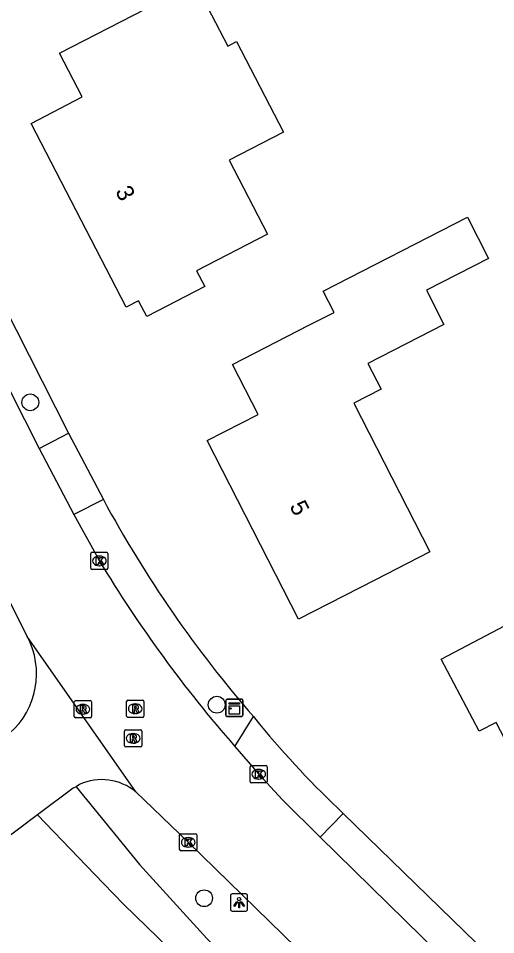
# Model space of a CAD drawing. Extents: x 162722 to 165099, y 384721 to 386283.
# Drawn here: x 163702.6 to 163730.3, y 384930.1 to 384983.4 of the extents above; entities that cross this region are included whole.
import ezdxf

# ---------------------------------------------------------------- set-up
doc = ezdxf.new("R2010")
doc.units = 0
for name, color, linetype in [('IMGEO_Boom', 7, 'Continuous'), ('IMGEO_Kast', 7, 'Continuous'), ('IMGEO_Kolk', 7, 'Continuous'), ('IMGEO_Lichtpunt', 7, 'Continuous'), ('IMGEO_Pand', 7, 'Continuous'), ('IMGEO_Pand_nummerreeks', 7, 'Continuous'), ('IMGEO_Parkeervlak_open', 7, 'Continuous'), ('IMGEO_Rijbaan_lokaal_open', 7, 'Continuous'), ('IMGEO_Rioolput', 7, 'Continuous'), ('IMGEO_Voetpad_open', 7, 'Continuous')]:
    doc.layers.add(name, color=color, linetype=linetype)

msp = doc.modelspace()

# ---------------------------------------------------------------- linework, layer by layer
at = {"layer": 'IMGEO_Boom'}
for centre in [(163703.26, 384961.042), (163714.111, 384943.457), (163713.375, 384932.201)]:
    msp.add_circle(centre, 0.489, dxfattribs=at)
at = {"layer": 'IMGEO_Kast'}
for p, q in [((163714.639, 384942.85), (163714.639, 384943.691)), ((163714.639, 384943.691), (163714.639, 384942.85)), ((163714.714, 384943.775), (163715.555, 384943.775)), ((163715.555, 384943.775), (163714.714, 384943.775)), ((163715.639, 384943.7), (163715.639, 384942.859)), ((163715.639, 384942.859), (163715.639, 384943.7)), ((163715.564, 384942.775), (163714.723, 384942.775)), ((163714.723, 384942.775), (163715.564, 384942.775))]:
    msp.add_line(p, q, dxfattribs=at)
for points in [[(163714.834, 384943.565), (163715.434, 384943.565), (163715.434, 384943.48), (163714.834, 384943.48), (163714.834, 384943.565)], [(163714.834, 384943.39), (163715.434, 384943.39), (163715.434, 384942.901), (163714.834, 384942.901), (163714.834, 384943.39)]]:
    msp.add_lwpolyline(points, dxfattribs=at)
msp.add_circle((163714.918, 384943.239), 0.0377, dxfattribs=at)
for centre, start, end in [((163714.717, 384943.697), 92.4484, 184.2845), ((163714.717, 384943.697), 92.4484, 184.2845), ((163715.561, 384943.697), 2.4484, 94.2845), ((163715.561, 384943.697), 2.4484, 94.2845), ((163714.717, 384942.853), 182.4484, 274.2845), ((163714.717, 384942.853), 182.4484, 274.2845), ((163715.561, 384942.853), 272.4484, 4.2845), ((163715.561, 384942.853), 272.4484, 4.2845)]:
    msp.add_arc(centre, 0.0779, start, end, dxfattribs=at)
at = {"layer": 'IMGEO_Kolk'}
for p, q in [((163706.78, 384951.395), (163706.78, 384952.247)), ((163706.855, 384952.321), (163707.707, 384952.321)), ((163707.268, 384952.101), (163707.293, 384952.101)), ((163707.781, 384952.247), (163707.781, 384951.395)), ((163707.291, 384951.541), (163707.266, 384951.541)), ((163707.707, 384951.321), (163706.855, 384951.321)), ((163716.051, 384938.988), (163716.051, 384939.84)), ((163716.126, 384939.914), (163716.978, 384939.914)), ((163716.539, 384939.694), (163716.564, 384939.694)), ((163717.052, 384939.84), (163717.052, 384938.988)), ((163716.562, 384939.134), (163716.537, 384939.134)), ((163716.978, 384938.914), (163716.126, 384938.914)), ((163712.026, 384935.954), (163712.878, 384935.954)), ((163711.951, 384935.028), (163711.951, 384935.88)), ((163712.439, 384935.734), (163712.464, 384935.734)), ((163712.952, 384935.88), (163712.952, 384935.028)), ((163712.878, 384934.954), (163712.026, 384934.954)), ((163712.462, 384935.174), (163712.437, 384935.174))]:
    msp.add_line(p, q, dxfattribs=at)
for points in [[(163706.78, 384951.395), (163706.78, 384952.247)], [(163706.855, 384952.321), (163707.707, 384952.321)], [(163707.101, 384952.021), (163707.224, 384952.021), (163707.224, 384951.87), (163707.354, 384952.021), (163707.518, 384952.021), (163707.372, 384951.87), (163707.525, 384951.621), (163707.373, 384951.621), (163707.288, 384951.785), (163707.224, 384951.718), (163707.224, 384951.621), (163707.101, 384951.621), (163707.101, 384952.021)], [(163707.781, 384952.247), (163707.781, 384951.395)], [(163707.707, 384951.321), (163706.855, 384951.321)], [(163716.051, 384938.988), (163716.051, 384939.84)], [(163716.126, 384939.914), (163716.978, 384939.914)], [(163717.052, 384939.84), (163717.052, 384938.988)], [(163716.372, 384939.614), (163716.495, 384939.614), (163716.495, 384939.463), (163716.625, 384939.614), (163716.789, 384939.614), (163716.643, 384939.463), (163716.796, 384939.214), (163716.644, 384939.214), (163716.559, 384939.378), (163716.495, 384939.311), (163716.495, 384939.214), (163716.372, 384939.214), (163716.372, 384939.614)], [(163716.978, 384938.914), (163716.126, 384938.914)], [(163712.026, 384935.954), (163712.878, 384935.954)], [(163711.951, 384935.028), (163711.951, 384935.88)], [(163712.272, 384935.654), (163712.395, 384935.654), (163712.395, 384935.503), (163712.525, 384935.654), (163712.689, 384935.654), (163712.543, 384935.503), (163712.696, 384935.254), (163712.544, 384935.254), (163712.459, 384935.418), (163712.395, 384935.351), (163712.395, 384935.254), (163712.272, 384935.254), (163712.272, 384935.654)], [(163712.952, 384935.88), (163712.952, 384935.028)], [(163712.878, 384934.954), (163712.026, 384934.954)]]:
    msp.add_lwpolyline(points, dxfattribs=at)
for centre, start, end in [((163706.857, 384952.245), 91.552, 178.448), ((163706.857, 384952.245), 91.552, 178.448), ((163707.705, 384952.245), 1.552, 88.448), ((163707.705, 384952.245), 1.552, 88.448), ((163706.857, 384951.397), 181.552, 268.448), ((163706.857, 384951.397), 181.552, 268.448), ((163707.705, 384951.397), 271.552, 358.448), ((163707.705, 384951.397), 271.552, 358.448), ((163716.128, 384939.838), 91.552, 178.448), ((163716.128, 384939.838), 91.552, 178.448), ((163716.976, 384939.838), 1.552, 88.448), ((163716.976, 384939.838), 1.552, 88.448), ((163716.128, 384938.99), 181.552, 268.448), ((163716.128, 384938.99), 181.552, 268.448), ((163716.976, 384938.99), 271.552, 358.448), ((163716.976, 384938.99), 271.552, 358.448), ((163712.028, 384935.878), 91.552, 178.448), ((163712.028, 384935.878), 91.552, 178.448), ((163712.876, 384935.878), 1.552, 88.448), ((163712.876, 384935.878), 1.552, 88.448), ((163712.028, 384935.03), 181.552, 268.448), ((163712.028, 384935.03), 181.552, 268.448), ((163712.876, 384935.03), 271.552, 358.448), ((163712.876, 384935.03), 271.552, 358.448)]:
    msp.add_arc(centre, 0.0765, start, end, dxfattribs=at)
for centre, major_axis, ratio, start_param, end_param in [((163707.267, 384951.821), (-0.387, 0.002), 0.722429, 4.712389, 7.853982), ((163707.292, 384951.821), (-0.39, 0.002), 0.717154, 1.570796, 4.712389), ((163716.538, 384939.414), (-0.387, 0.002), 0.722429, 4.712389, 7.853982), ((163716.563, 384939.414), (-0.39, 0.002), 0.717154, 1.570796, 4.712389), ((163712.438, 384935.454), (-0.387, 0.002), 0.722429, 4.712389, 7.853982), ((163712.463, 384935.454), (-0.39, 0.002), 0.717154, 1.570796, 4.712389)]:
    msp.add_ellipse(centre, major_axis=major_axis, ratio=ratio, start_param=start_param, end_param=end_param, dxfattribs=at)
at = {"layer": 'IMGEO_Lichtpunt'}
for p, q in [((163714.912, 384932.354), (163714.912, 384931.547)), ((163714.912, 384932.354), (163714.912, 384931.547)), ((163715.814, 384932.449), (163715.006, 384932.449)), ((163715.814, 384932.449), (163715.006, 384932.449)), ((163715.908, 384931.547), (163715.908, 384932.354)), ((163715.908, 384931.547), (163715.908, 384932.354)), ((163715.006, 384931.453), (163715.814, 384931.453)), ((163715.006, 384931.453), (163715.814, 384931.453))]:
    msp.add_line(p, q, dxfattribs=at)
for points in [[(163715.286, 384932.018), (163715.325, 384931.99), (163715.137, 384931.728), (163715.099, 384931.755), (163715.286, 384932.018)], [(163715.388, 384931.97), (163715.435, 384931.97), (163715.435, 384931.648), (163715.388, 384931.648), (163715.388, 384931.97)], [(163715.498, 384931.99), (163715.536, 384932.017), (163715.723, 384931.755), (163715.684, 384931.727), (163715.498, 384931.99)]]:
    msp.add_lwpolyline(points, dxfattribs=at)
msp.add_circle((163715.411, 384932.152), 0.0994, dxfattribs=at)
for centre, start, end in [((163715.006, 384932.354), 90, 180), ((163715.006, 384932.354), 90, 180), ((163715.814, 384932.354), 0, 90), ((163715.814, 384932.354), 0, 90), ((163715.006, 384931.547), 180, 270), ((163715.006, 384931.547), 180, 270), ((163715.814, 384931.547), 270, 0), ((163715.814, 384931.547), 270, 360)]:
    msp.add_arc(centre, 0.0946, start, end, dxfattribs=at)
at = {"layer": 'IMGEO_Pand'}
for points in [[(163717.064, 384970.82), (163712.943, 384968.69), (163713.412, 384967.784), (163710.036, 384966.039), (163709.567, 384966.945), (163708.838, 384966.568), (163703.306, 384977.267), (163706.282, 384978.806), (163704.968, 384981.348), (163712.859, 384985.428), (163714.756, 384981.76), (163715.26, 384982.021), (163717.987, 384976.746), (163714.841, 384975.12), (163717.064, 384970.82)], [(163723.674, 384961.809), (163722.095, 384961.001), (163726.522, 384952.344), (163723.316, 384950.705), (163718.864, 384948.428), (163713.554, 384958.814), (163716.515, 384960.328), (163715.022, 384963.248), (163719.474, 384965.524), (163720.939, 384966.273), (163720.309, 384967.506), (163728.714, 384971.805), (163729.935, 384969.416), (163726.31, 384967.563), (163727.329, 384965.57), (163722.908, 384963.308), (163723.674, 384961.809)], [(163739.111, 384952.379), (163740.984, 384948.815), (163741.129, 384948.539), (163739.187, 384947.518), (163738.217, 384947.008), (163738.524, 384946.424), (163741.959, 384939.889), (163741.39, 384939.59), (163743.129, 384936.283), (163737.685, 384933.421), (163735.947, 384936.728), (163733.919, 384935.662), (163731.932, 384939.443), (163730.365, 384942.425), (163729.381, 384941.909), (163727.176, 384946.104), (163737.169, 384951.358), (163739.111, 384952.379)]]:
    msp.add_lwpolyline(points, dxfattribs=at)
at = {"layer": 'IMGEO_Parkeervlak_open'}
for points in [[(163697.839, 384974.289), (163705.48, 384959.251)], [(163721.477, 384937.136), (163732.746, 384926.182)]]:
    msp.add_lwpolyline(points, dxfattribs=at)
msp.add_arc((163768.629, 384988.383), 69.456, 208.36529, 221.05428, dxfattribs=at)
at = {"layer": 'IMGEO_Rijbaan_lokaal_open'}
for points in [[(163696.103, 384973.454), (163699.534, 384966.704), (163703.768, 384958.355)], [(163703.768, 384958.355), (163705.797, 384954.524)], [(163703.08, 384947.428), (163701.856, 384949.895), (163699.111, 384955.206)], [(163705.797, 384954.524), (163707.281, 384951.821)], [(163709.401, 384938.391), (163703.08, 384947.428)], [(163715.161, 384941.031), (163716.552, 384939.414), (163717.931, 384937.92), (163720.131, 384935.757)], [(163705.921, 384938.688), (163705.755, 384938.594), (163703.684, 384937.056)], [(163706.129, 384938.825), (163705.921, 384938.688)], [(163726.925, 384921.347), (163725.854, 384922.399), (163712.452, 384935.454), (163709.401, 384938.391)], [(163703.684, 384937.056), (163680.028, 384919.248)], [(163720.131, 384935.757), (163729.987, 384926.103)]]:
    msp.add_lwpolyline(points, dxfattribs=at)
for centre, radius, start, end in [((163772.984, 384991.532), 76.771, 211.14873, 221.13302), ((163699.026, 384945.257), 4.599, 311.2828, 28.1684), ((163707.415, 384935.969), 3.132, 50.6445, 114.2442)]:
    msp.add_arc(centre, radius, start, end, dxfattribs=at)
at = {"layer": 'IMGEO_Rioolput'}
for p, q in [((163705.823, 384942.767), (163705.823, 384943.619)), ((163705.898, 384943.693), (163706.75, 384943.693)), ((163706.311, 384943.473), (163706.336, 384943.473)), ((163706.824, 384943.619), (163706.824, 384942.767)), ((163708.867, 384942.797), (163708.867, 384943.649)), ((163708.942, 384943.723), (163709.794, 384943.723)), ((163709.355, 384943.503), (163709.38, 384943.503)), ((163709.868, 384943.649), (163709.868, 384942.797)), ((163706.334, 384942.913), (163706.309, 384942.913)), ((163709.378, 384942.943), (163709.353, 384942.943)), ((163706.75, 384942.693), (163705.898, 384942.693)), ((163709.794, 384942.723), (163708.942, 384942.723)), ((163708.744, 384941.074), (163708.744, 384941.926)), ((163708.819, 384942), (163709.671, 384942)), ((163709.745, 384941.926), (163709.745, 384941.074)), ((163709.232, 384941.78), (163709.257, 384941.78)), ((163709.671, 384941), (163708.819, 384941)), ((163709.255, 384941.22), (163709.23, 384941.22))]:
    msp.add_line(p, q, dxfattribs=at)
for points in [[(163705.823, 384942.767), (163705.823, 384943.619)], [(163705.898, 384943.693), (163706.75, 384943.693)], [(163706.824, 384943.619), (163706.824, 384942.767)], [(163708.867, 384942.797), (163708.867, 384943.649)], [(163708.942, 384943.723), (163709.794, 384943.723)], [(163709.456, 384943.421), (163709.204, 384943.423), (163709.204, 384943.023)], [(163709.868, 384943.649), (163709.868, 384942.797)], [(163706.412, 384943.391), (163706.16, 384943.393), (163706.16, 384942.993)], [(163706.16, 384942.993), (163706.284, 384942.993), (163706.284, 384943.155), (163706.295, 384943.155)], [(163706.338, 384943.312), (163706.284, 384943.312), (163706.284, 384943.231)], [(163706.284, 384943.231), (163706.336, 384943.231)], [(163706.342, 384943.126), (163706.413, 384942.993), (163706.553, 384942.993), (163706.488, 384943.119)], [(163709.204, 384943.023), (163709.328, 384943.023), (163709.328, 384943.185), (163709.339, 384943.185)], [(163709.382, 384943.342), (163709.328, 384943.342), (163709.328, 384943.261)], [(163709.328, 384943.261), (163709.38, 384943.261)], [(163709.386, 384943.156), (163709.457, 384943.023), (163709.597, 384943.023), (163709.532, 384943.149)], [(163706.75, 384942.693), (163705.898, 384942.693)], [(163709.794, 384942.723), (163708.942, 384942.723)], [(163708.744, 384941.074), (163708.744, 384941.926)], [(163708.819, 384942), (163709.671, 384942)], [(163709.745, 384941.926), (163709.745, 384941.074)], [(163709.333, 384941.698), (163709.081, 384941.7), (163709.081, 384941.3)], [(163709.081, 384941.3), (163709.205, 384941.3), (163709.205, 384941.462), (163709.216, 384941.462)], [(163709.259, 384941.619), (163709.205, 384941.619), (163709.205, 384941.538)], [(163709.205, 384941.538), (163709.257, 384941.538)], [(163709.263, 384941.433), (163709.334, 384941.3), (163709.474, 384941.3), (163709.409, 384941.426)], [(163709.671, 384941), (163708.819, 384941)]]:
    msp.add_lwpolyline(points, dxfattribs=at)
for centre, radius, start, end in [((163705.9, 384943.617), 0.0765, 91.552, 178.448), ((163705.9, 384943.617), 0.0765, 91.552, 178.448), ((163706.748, 384943.617), 0.0765, 1.552, 88.448), ((163706.748, 384943.617), 0.0765, 1.552, 88.448), ((163708.944, 384943.647), 0.0765, 91.552, 178.448), ((163708.944, 384943.647), 0.0765, 91.552, 178.448), ((163709.455, 384943.311), 0.109, 350.3612, 89.416), ((163709.792, 384943.647), 0.0765, 1.552, 88.448), ((163709.792, 384943.647), 0.0765, 1.552, 88.448), ((163706.294, 384943.102), 0.0533, 26.0293, 88.6989), ((163706.32, 384943.42), 0.19, 274.7715, 282.9687), ((163706.344, 384943.216), 0.0964, 77.0061, 93.1865), ((163706.358, 384943.273), 0.0378, 276.6634, 79.6772), ((163706.411, 384943.281), 0.109, 350.3612, 89.416), ((163706.409, 384943.281), 0.112, 277.5842, 350.9817), ((163706.393, 384943.066), 0.108, 29.5134, 73.7905), ((163709.338, 384943.132), 0.0533, 26.0293, 88.6989), ((163709.364, 384943.45), 0.19, 274.7715, 282.9687), ((163709.388, 384943.246), 0.0964, 77.0061, 93.1865), ((163709.402, 384943.303), 0.0378, 276.6634, 79.6772), ((163709.453, 384943.311), 0.112, 277.5842, 350.9817), ((163709.437, 384943.096), 0.108, 29.5134, 73.7905), ((163705.9, 384942.769), 0.0765, 181.552, 268.448), ((163705.9, 384942.769), 0.0765, 181.552, 268.448), ((163706.748, 384942.769), 0.0765, 271.552, 358.448), ((163706.748, 384942.769), 0.0765, 271.552, 358.448), ((163708.944, 384942.799), 0.0765, 181.552, 268.448), ((163708.944, 384942.799), 0.0765, 181.552, 268.448), ((163709.792, 384942.799), 0.0765, 271.552, 358.448), ((163709.792, 384942.799), 0.0765, 271.552, 358.448), ((163708.821, 384941.924), 0.0765, 91.552, 178.448), ((163708.821, 384941.924), 0.0765, 91.552, 178.448), ((163709.669, 384941.924), 0.0765, 1.552, 88.448), ((163709.669, 384941.924), 0.0765, 1.552, 88.448), ((163709.215, 384941.409), 0.0533, 26.0293, 88.6989), ((163709.241, 384941.727), 0.19, 274.7715, 282.9687), ((163709.265, 384941.523), 0.0964, 77.0061, 93.1865), ((163709.279, 384941.58), 0.0378, 276.6634, 79.6772), ((163709.332, 384941.588), 0.109, 350.3612, 89.416), ((163709.33, 384941.588), 0.112, 277.5842, 350.9817), ((163709.314, 384941.373), 0.108, 29.5134, 73.7905), ((163708.821, 384941.076), 0.0765, 181.552, 268.448), ((163708.821, 384941.076), 0.0765, 181.552, 268.448), ((163709.669, 384941.076), 0.0765, 271.552, 358.448), ((163709.669, 384941.076), 0.0765, 271.552, 358.448)]:
    msp.add_arc(centre, radius, start, end, dxfattribs=at)
for centre, major_axis, ratio, start_param, end_param in [((163706.31, 384943.193), (-0.387, 0.002), 0.722429, 4.712389, 7.853982), ((163706.335, 384943.193), (-0.39, 0.002), 0.717154, 1.570796, 4.712389), ((163709.354, 384943.223), (-0.387, 0.002), 0.722429, 4.712389, 7.853982), ((163709.379, 384943.223), (-0.39, 0.002), 0.717154, 1.570796, 4.712389), ((163709.231, 384941.5), (-0.387, 0.002), 0.722429, 4.712389, 7.853982), ((163709.256, 384941.5), (-0.39, 0.002), 0.717154, 1.570796, 4.712389)]:
    msp.add_ellipse(centre, major_axis=major_axis, ratio=ratio, start_param=start_param, end_param=end_param, dxfattribs=at)
at = {"layer": 'IMGEO_Voetpad_open'}
for points in [[(163703.768, 384958.355), (163705.48, 384959.251)], [(163705.48, 384959.251), (163707.512, 384955.385)], [(163707.512, 384955.385), (163705.797, 384954.524)], [(163715.161, 384941.031), (163716.253, 384942.766)], [(163716.253, 384942.766), (163716.604, 384942.317)], [(163705.921, 384938.688), (163709.613, 384934.17), (163713.526, 384929.868), (163724.619, 384919.117)], [(163723.266, 384917.713), (163708.711, 384931.843), (163707.497, 384933.071), (163703.684, 384937.056)], [(163721.477, 384937.136), (163720.131, 384935.757)]]:
    msp.add_lwpolyline(points, dxfattribs=at)
msp.add_arc((163761.015, 384979.205), 57.733, 219.7137, 226.77694, dxfattribs=at)

# ---------------------------------------------------------------- texts
at = {"layer": 'IMGEO_Pand_nummerreeks'}
for s, rotation, p in [('3', 297.3416, (163708.184, 384973.319)), ('5', 297.0778, (163718.327, 384955.013))]:
    msp.add_text(s, height=1, rotation=rotation, dxfattribs=at).set_placement(p)

doc.saveas('drawing.dxf')
